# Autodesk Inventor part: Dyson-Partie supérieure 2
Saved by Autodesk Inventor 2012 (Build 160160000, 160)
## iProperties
Created: 2012-11
Part Number: Dyson-Partie supérieure 2
Material: Default
Document SubType Name: Modeling
Designer: Administrateur
Density: 1 g/cm^3
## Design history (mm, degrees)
node "Dyson-Partie supérieure 21"
node "Dyson-Partie supérieure 2"
node "Base1"
